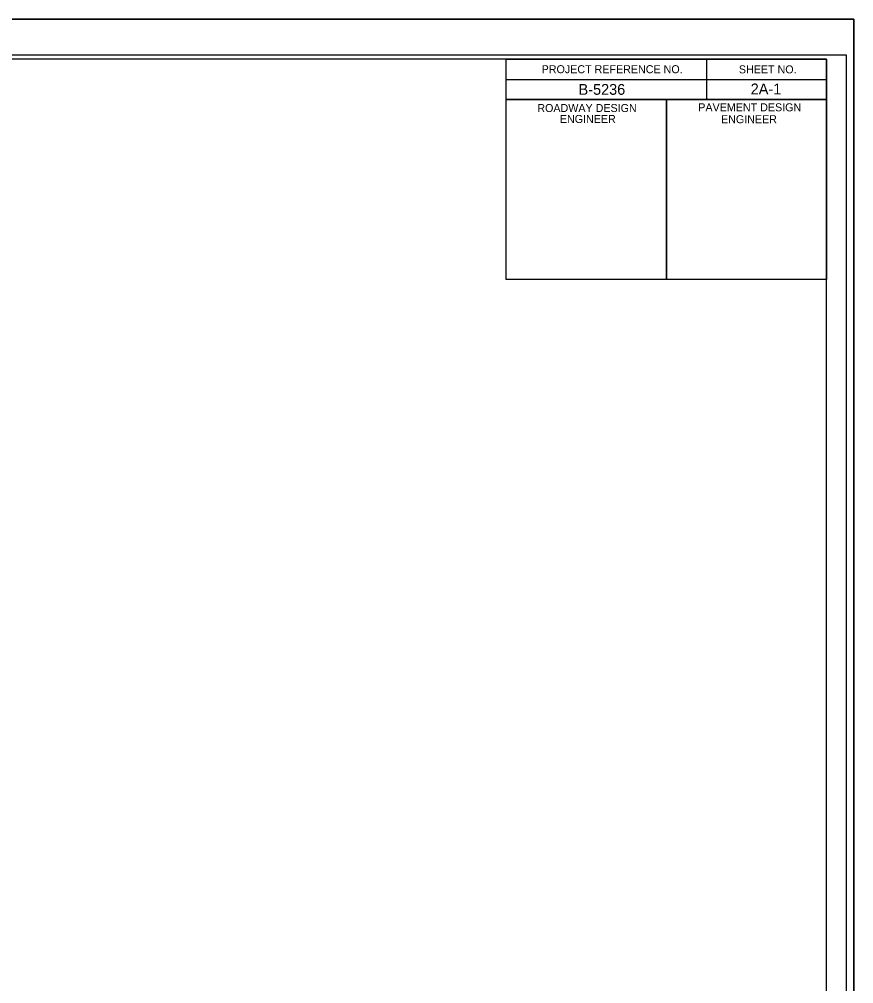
# Model space of a CAD drawing. Extents: x 1733676 to 1734289, y 540979 to 541226.
# Drawn here: x 1733802.1 to 1733858.3, y 541033.1 to 541098.2 of the extents above; entities that cross this region are included whole.
import ezdxf

# ---------------------------------------------------------------- set-up
doc = ezdxf.new("R2010")
doc.units = 0
for name, color, linetype in [('Prop Dimension', 7, 'Continuous'), ('Sheet Cutting Line CELL', 7, 'Continuous'), ('Sheet Data Field CELL', 7, 'Continuous'), ('Sheet Plot Border Inside CELL', 7, 'Continuous'), ('Sheet Plot Border Outside CELL', 7, 'Continuous'), ('Sheet Typical CELL', 7, 'Continuous')]:
    doc.layers.add(name, color=color, linetype=linetype)

msp = doc.modelspace()

# ---------------------------------------------------------------- linework, layer by layer
at = {"layer": 'Prop Dimension'}
msp.add_lwpolyline([(1733676.466, 541098.221), (1733858.338, 541098.221), (1733858.338, 540979.421), (1733676.466, 540979.421)], close=True, dxfattribs=at)
msp.add_lwpolyline([(1733676.466, 541098.221), (1733858.338, 541098.221), (1733858.338, 540979.421), (1733676.466, 540979.421)], close=True, dxfattribs=at)
at = {"layer": 'Sheet Cutting Line CELL'}
msp.add_line((1733858.338, 541098.221), (1733676.466, 541098.221), dxfattribs=at)
at = {"layer": 'Sheet Plot Border Inside CELL'}
msp.add_lwpolyline([(1733857.852, 541095.797), (1733677.87, 541095.797), (1733677.87, 540981.846), (1733857.852, 540981.846)], close=True, dxfattribs=at)
at = {"layer": 'Sheet Plot Border Outside CELL'}
msp.add_lwpolyline([(1733858.338, 541098.221), (1733676.466, 541098.221), (1733676.466, 540979.421), (1733858.338, 540979.421)], close=True, dxfattribs=at)
at = {"layer": 'Sheet Typical CELL'}
for p, q in [((1733848.402, 541095.516), (1733848.402, 541092.816)), ((1733834.897, 541094.166), (1733856.502, 541094.166)), ((1733845.702, 541092.816), (1733845.702, 541080.671))]:
    msp.add_line(p, q, dxfattribs=at)
for points in [[(1733856.502, 541095.521), (1733694.502, 541095.521), (1733694.502, 540982.121), (1733856.502, 540982.121)], [(1733834.897, 541095.521), (1733856.502, 541095.521), (1733856.502, 541092.816), (1733834.897, 541092.816)], [(1733834.897, 541092.816), (1733845.702, 541092.816), (1733845.702, 541080.666), (1733834.897, 541080.666)], [(1733845.702, 541092.816), (1733856.502, 541092.816), (1733856.502, 541080.666), (1733845.702, 541080.666)]]:
    msp.add_lwpolyline(points, close=True, dxfattribs=at)

# ---------------------------------------------------------------- texts
at = {"layer": 'Sheet Data Field CELL'}
for s, p in [('B-5236', (1733839.786, 541093.124)), ('2A-1', (1733851.392, 541093.156))]:
    msp.add_text(s, height=0.729, dxfattribs=at).set_placement(p)
at = {"layer": 'Sheet Typical CELL'}
for s, height, p in [('PROJECT REFERENCE NO.', 0.54001, (1733837.294, 541094.582)), ('SHEET NO.', 0.54, (1733850.594, 541094.571)), ('ROADWAY DESIGN', 0.54001, (1733837.003, 541091.963)), ('PAVEMENT DESIGN', 0.54001, (1733847.857, 541092.011)), ('ENGINEER', 0.54, (1733838.52, 541091.223)), ('ENGINEER', 0.54, (1733849.39, 541091.207))]:
    msp.add_text(s, height=height, dxfattribs=at).set_placement(p)

doc.saveas('drawing.dxf')
